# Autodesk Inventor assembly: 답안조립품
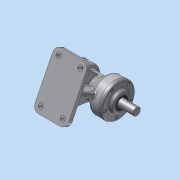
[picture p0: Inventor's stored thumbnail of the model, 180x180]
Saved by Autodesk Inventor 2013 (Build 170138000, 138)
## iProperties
Created: 2015-08
Part Number: 답안조립품
Document SubType Name: Assembly
Designer: Administrator
Author: Administrator
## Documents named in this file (10)
- C:\Users\Administrator\Desktop\450806V1009\답안조립품.iam
- C:\Users\Administrator\Desktop\450806V1009\M4x0.5.ipt
- C:\Users\Administrator\Desktop\450806V1009\뒤커버.ipt
- C:\Users\Administrator\Desktop\450806V1009\베어링 6203.ipt
- C:\Users\Administrator\Desktop\450806V1009\베어링 6205.ipt
- C:\Users\Administrator\Desktop\450806V1009\본체.ipt
- C:\Users\Administrator\Desktop\450806V1009\앞커버.ipt
- C:\Users\Administrator\Desktop\450806V1009\오일실 .ipt
- 오일실 .ipt
- C:\Users\Administrator\Desktop\450806V1009\축.ipt
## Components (10 placed, 1 different names)
1. M4x0.5:2
2. M4x0.5:1
3. M4x0.5:3
4. M4x0.5:4
5. M4x0.5:5
6. M4x0.5:6
7. M4x0.5:7
8. M4x0.5:8
9. M4x0.5:9
10. M4x0.5:10
